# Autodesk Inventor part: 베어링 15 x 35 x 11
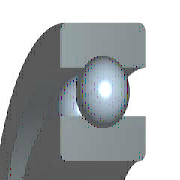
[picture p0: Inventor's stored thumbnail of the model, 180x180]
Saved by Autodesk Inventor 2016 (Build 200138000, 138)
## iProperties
Created: 2012-02
Part Number: 베어링 15 x 35 x 11
Material: 강철, 연강
Description: 깊은 그루브 볼 베어링
Document SubType Name: Modeling
Standard: KS B 2023
Designer: mduedu
Standards Organization: KS
Language: ko-KR
Size Designation: 6202 - 15 x 35 x 11
Categories: <MemberInstance><Categories><Category DisplayName="샤프트 부품" InternalName="7f7aeb1f-a693-4053-b835-cee3144e0d98" Mnemonic="SHFT"><Category DisplayName="베어링" Inter
Density: 1 g/cm^3
Appearance: 강철
IsCustomPart: 1
Author: mduedu
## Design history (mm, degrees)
sketch "스케치" dims "d0" = 5.2 (= -0.26 x WD + 0.26 x BD)
  geometry: L1 (2.9, 12.5)-(8.1, 12.5); L2 (5.5, 12.5)-(5.5, 9.9); L3 (5.5, 12.5)-(5.5, 15.1); L4 (3.568, 10.76)-(0, 10.76); L5 (0, 7.5)-(11, 7.5); L6 (3.568, 14.24)-(0, 14.24); L7 (0, 17.5)-(11, 17.5); L8 (11, 7.5)-(11, 10.76); L9 (7.432, 10.76)-(11, 10.76); L10 (7.432, 14.24)-(11, 14.24); L11 (11, 17.5)-(11, 14.24); L12 (-1.4, 0)-(8.4, 0) reference; L13 (0, -0.3)-(0, 5.3) reference
  constraints: 22 end point, 4 point on line, 2 collinear, 2 perpendicular, 2 symmetric about line, 1 midpoint, 1 parallel, 14 other
  dimensions: "d9" = 15 diameter of L5 L12 (= WD); "d11" = 35 diameter of L7 L12 (= BD); "d12" = 11 distance between parallel lines of L8 L13 (= KB); "d13" = 21.52 diameter of L9 L12 (= 0.326 x BD + 0.674 x WD)
revolve "본체" stored, may be unused: angle "d6" = 90 deg
revolve "볼" stored, may be unused: angle "d7" = 90 deg
pattern_circular "IDS_ARRAYBALL[SIMPL:T]" dims angle "d3" = 360 deg
body "Solid1"
fillet "모깎기1" dims "d1" = 0.6 (= KRS)
other parameters: "WD" = 15 [user parameter; used in 5 equation terms], "BD" = 35 [user parameter; used in 5 equation terms], "KB" = 11 [user parameter; used in 1 equation term], "KRS" = 0.6 [user parameter; used in 1 equation term], "d4" = 0, "d5" = 0, "d8" = 0, "d14" = 0, "d15" = 0, "BBA" = 0 [user parameter], "BC0" = 3750000 [user parameter], "BC" = 7800000 [user parameter], "BR" = 17.5 (= 0.5 x BD) [user parameter], "WR" = 7.5 (= 0.5 x WD) [user parameter]
